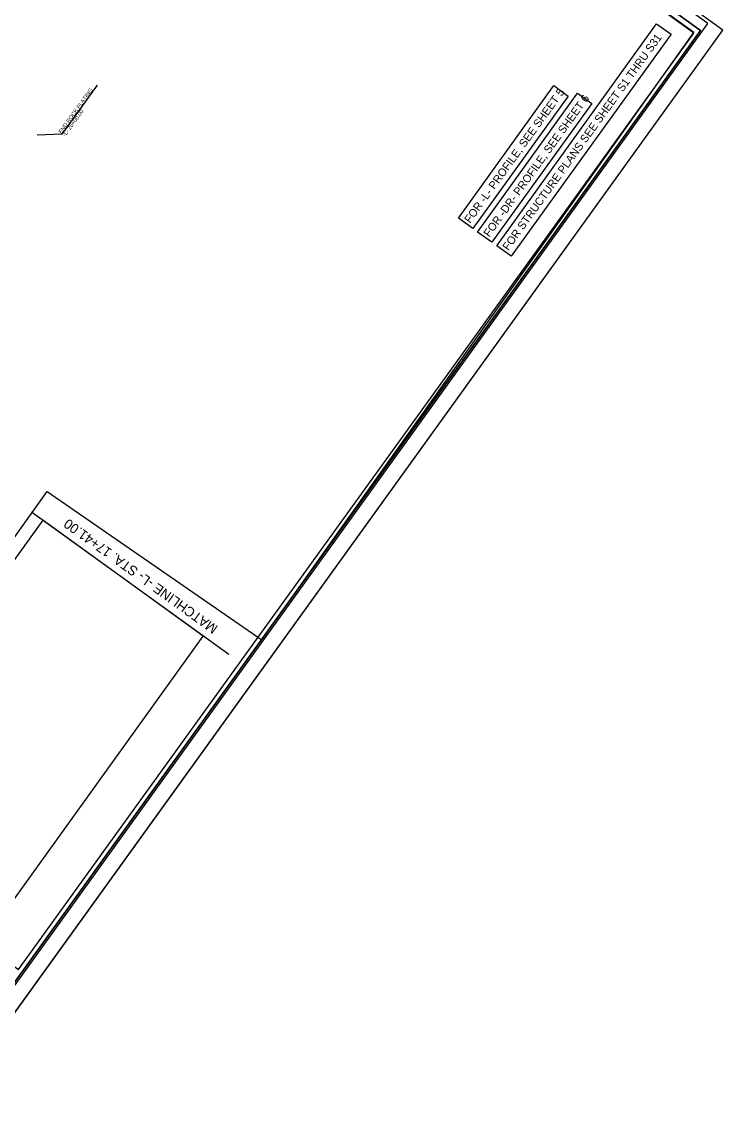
# Model space of a CAD drawing. Extents: x 2186840 to 2191350, y 386817 to 390793.
# Drawn here: x 2190474 to 2191350, y 386817 to 388192 of the extents above; entities that cross this region are included whole.
import ezdxf

# ---------------------------------------------------------------- set-up
doc = ezdxf.new("R2010")
doc.units = 0
for name, color, linetype in [('Matchline', 7, 'Continuous'), ('Matchline Text', 7, 'Continuous'), ('Prop Geotechnical Rock Plating Label', 7, 'Continuous'), ('Prop PHM Label Text', 7, 'Continuous'), ('Sheet Clip Boundary CELL', 7, 'Continuous'), ('Sheet Cutting Line CELL', 7, 'Continuous'), ('Sheet Data Field CELL', 7, 'Continuous'), ('Sheet Layout Plan Border', 7, 'Continuous'), ('Sheet Plan CELL', 7, 'Continuous'), ('Sheet Plan Layout CELL', 7, 'Continuous'), ('Sheet Plot Border Inside CELL', 7, 'Continuous'), ('Sheet Plot Border Outside CELL', 7, 'Continuous')]:
    doc.layers.add(name, color=color, linetype=linetype)

msp = doc.modelspace()

# ---------------------------------------------------------------- linework, layer by layer
at = {"layer": 'Matchline'}
msp.add_line((2190732.4, 387402.2), (2190486, 387579.8), dxfattribs=at)
at = {"layer": 'Prop Geotechnical Rock Plating Label'}
for p, q in [((2190567.9, 388113.4), (2190523.7, 388052.1)), ((2190523.7, 388052.1), (2190492.9, 388050.9))]:
    msp.add_line(p, q, dxfattribs=at)
at = {"layer": 'Prop PHM Label Text'}
msp.add_lwpolyline([(2190499.9, 387569.8), (2190242.9, 387213.4), (2190443.6, 387068.6), (2190700.6, 387425.1)], close=True, dxfattribs=at)
at = {"layer": 'Sheet Clip Boundary CELL'}
msp.add_lwpolyline([(2189820.2, 387477.5), (2190138.1, 387247.7), (2190214.8, 387198.3), (2190505.6, 387605.8), (2190773.9, 387420.4), (2191313.5, 388179.1), (2190637.6, 388666.3), (2190501.9, 388478.1), (2190332.6, 388600.2), (2189623.6, 387618.7)], close=True, dxfattribs=at)
at = {"layer": 'Sheet Cutting Line CELL'}
msp.add_line((2190365.4, 386816.9), (2191350.1, 388182.3), dxfattribs=at)
at = {"layer": 'Sheet Data Field CELL'}
for points in [[(2191285.2, 388177), (2191085.3, 387899.8), (2191067.3, 387912.8), (2191267.2, 388189.9)], [(2191156.8, 388099.9), (2191037.4, 387934.3), (2191019.5, 387947.3), (2191138.9, 388112.9)], [(2191186.4, 388090.5), (2191061.4, 387917.1), (2191043.4, 387930), (2191168.5, 388103.4)]]:
    msp.add_lwpolyline(points, close=True, dxfattribs=at)
at = {"layer": 'Sheet Layout Plan Border'}
msp.add_lwpolyline([(2190469.7, 387008.5), (2191313.6, 388178.6), (2190637.9, 388666), (2190536.8, 388525.9), (2190366.5, 388648.8), (2189623.6, 387618.7)], close=True, dxfattribs=at)
at = {"layer": 'Sheet Plan CELL'}
for points in [[(2190470.3, 388795.9), (2189592.9, 387579.2), (2190444.5, 386965.1), (2191321.9, 388181.7)], [(2190444.5, 386965.1), (2189592.9, 387579.2), (2190353.3, 388633.6), (2190475, 388545.9), (2190592, 388708.1), (2191321.9, 388181.7)]]:
    msp.add_lwpolyline(points, close=True, dxfattribs=at)
at = {"layer": 'Sheet Plan Layout CELL'}
msp.add_lwpolyline([(2189592.9, 387579.2), (2190444.5, 386965.1), (2191321.9, 388181.7), (2190641.8, 388672.2), (2190501.9, 388478.1), (2190330.4, 388601.8)], close=True, dxfattribs=at)
at = {"layer": 'Sheet Plot Border Inside CELL'}
msp.add_lwpolyline([(2190356.8, 386839.1), (2191331.3, 388190.4), (2190475.6, 388807.5), (2189501.1, 387456.2)], close=True, dxfattribs=at)
at = {"layer": 'Sheet Plot Border Outside CELL'}
msp.add_lwpolyline([(2190365.4, 386816.9), (2191350.1, 388182.3), (2190462, 388822.8), (2189477.3, 387457.4)], close=True, dxfattribs=at)

# ---------------------------------------------------------------- texts
at = {"layer": 'Matchline Text'}
msp.add_text('MATCHLINE -L- STA. 17+41.00', height=12.15, rotation=144.2018, dxfattribs=at).set_placement((2190719.8, 387437))
at = {"layer": 'Prop Geotechnical Rock Plating Label'}
for s, p in [('END ROCK PLATING', (2190523.2, 388052.4)), ('-L- 26+00.00', (2190528.3, 388048.8))]:
    msp.add_text(s, height=5, rotation=54.2018, dxfattribs=at).set_placement(p)
at = {"layer": 'Sheet Data Field CELL'}
for s, p in [('FOR STRUCTURE PLANS SEE SHEET S1 THRU S31', (2191081.8, 387906)), ('FOR -L- PROFILE, SEE SHEET 5', (2191034.1, 387940.2)), ('FOR -DR- PROFILE, SEE SHEET 6', (2191058.1, 387922.9))]:
    msp.add_text(s, height=10, rotation=54.2018, dxfattribs=at).set_placement(p)

doc.saveas('drawing.dxf')
